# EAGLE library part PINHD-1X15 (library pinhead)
PIN HEADER
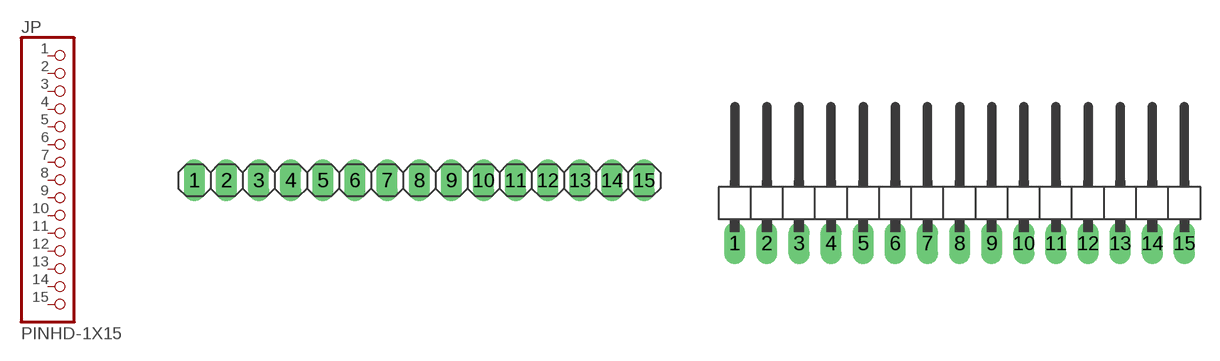
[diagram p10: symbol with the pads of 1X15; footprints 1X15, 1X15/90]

Designator prefix JP

## PINHD-1X15  [1X15]
1  1  pas
2  2  pas
3  3  pas
4  4  pas
5  5  pas
6  6  pas
7  7  pas
8  8  pas
9  9  pas
10  10  pas
11  11  pas
12  12  pas
13  13  pas
14  14  pas
15  15  pas

## PINHD-1X15/90  [1X15/90]
Pads as for 1X15

## Footprint 1X15 (pad centres in mm)
PIN HEADER
drill 1.016 pad 1.67 long: 1 -17.78,0; 2 -15.24,0; 3 -12.7,0; 4 -10.16,0; 5 -7.62,0; 6 -5.08,0; 7 -2.54,0; 8 0,0; 9 2.54,0; 10 5.08,0; 11 7.62,0; 12 10.16,0; 13 12.7,0; 14 15.24,0; 15 17.78,0

## Footprint 1X15/90 (pad centres in mm)
PIN HEADER
drill 1.016 pad 1.67 long: 1 -17.78,-3.81; 2 -15.24,-3.81; 3 -12.7,-3.81; 4 -10.16,-3.81; 5 -7.62,-3.81; 6 -5.08,-3.81; 7 -2.54,-3.81; 8 0,-3.81; 9 2.54,-3.81; 10 5.08,-3.81; 11 7.62,-3.81; 12 10.16,-3.81; 13 12.7,-3.81; 14 15.24,-3.81; 15 17.78,-3.81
